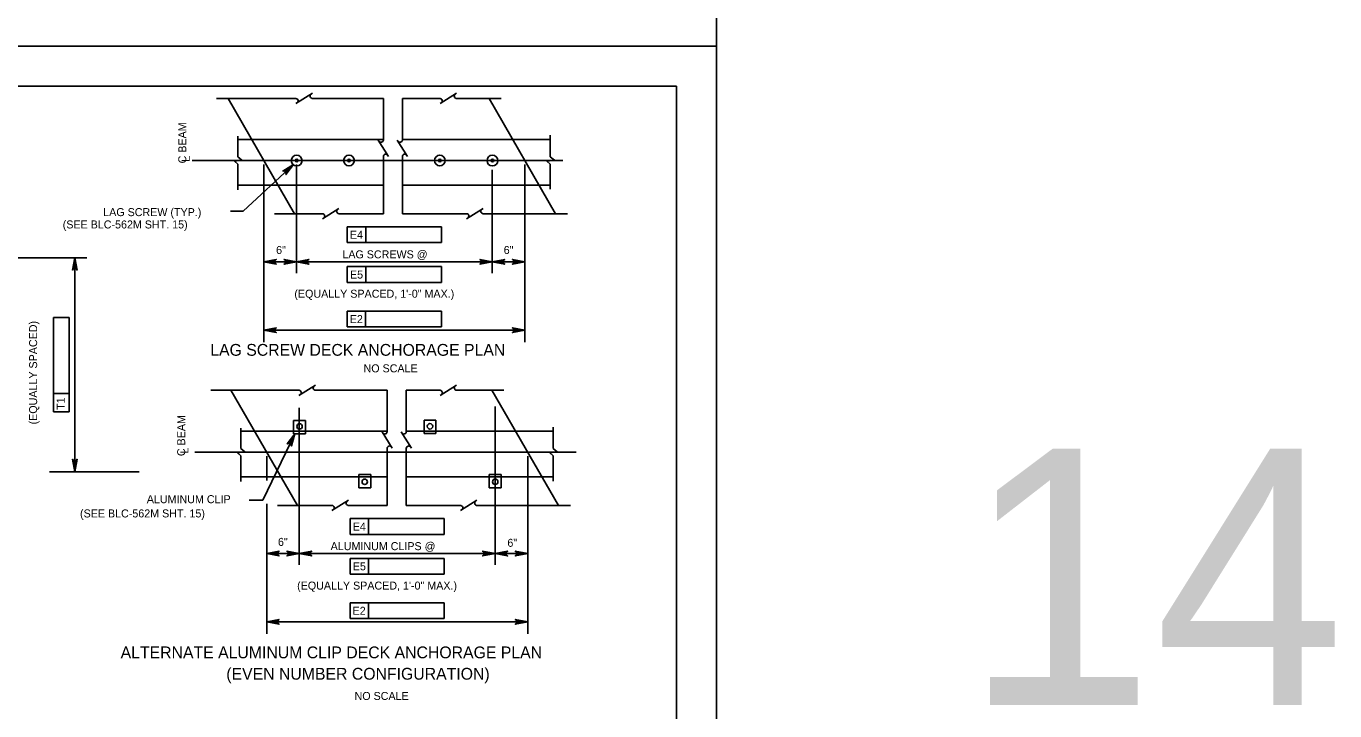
# Model space of a CAD drawing. Extents: x 638263 to 640391, y 293683 to 298655.
# Drawn here: x 639858.7 to 640349.2, y 295216.3 to 295473 of the extents above; entities that cross this region are included whole.
import ezdxf

# ---------------------------------------------------------------- set-up
doc = ezdxf.new("R2010")
doc.units = 0
for name, color, linetype in [('2', 7, 'Continuous'), ('3', 7, 'Continuous'), ('4', 7, 'Continuous'), ('8', 7, 'Continuous'), ('9', 7, 'Continuous'), ('PLT-BNDY', 7, 'Continuous')]:
    doc.layers.add(name, color=color, linetype=linetype)

# ---------------------------------------------------------------- blocks, each defined once
blk = doc.blocks.new('B')
at = {"layer": '3'}
blk.add_circle((0, 0), 0.16, dxfattribs=at)
for start, end in [(0, 180), (180, 0)]:
    blk.add_arc((0, 0), 0.0391, start, end, dxfattribs=at)

msp = doc.modelspace()

# ---------------------------------------------------------------- linework, layer by layer
at = {"layer": '2'}
for p, q in [((639316.46, 295450.46), (640102.46, 295450.46)), ((639934.36, 295445.85), (639959.32, 295402.67)), ((640032.19, 295445.85), (640057.16, 295402.67)), ((640102.46, 295450.46), (640102.46, 294886.46)), ((639935.42, 295336.5), (639960.38, 295293.31)), ((640033.25, 295336.5), (640058.22, 295293.31))]:
    msp.add_line(p, q, dxfattribs=at)
at = {"layer": '3'}
for p, q in [((639959.82, 295445.85), (639929.98, 295445.85)), ((639965.96, 295447.79), (639959.8, 295443.92)), ((639992.57, 295445.85), (639966.03, 295445.85)), ((639992.57, 295430.27), (639992.57, 295445.85)), ((639999.73, 295430.27), (639999.73, 295445.85)), ((640013.84, 295445.85), (639999.73, 295445.85)), ((640019.99, 295447.79), (640013.83, 295443.92)), ((640036.69, 295445.85), (640020.06, 295445.85)), ((639938.05, 295423.97), (639938.05, 295431.69)), ((640055.13, 295423.97), (640055.13, 295432.06)), ((639992.57, 295430.5), (639938.05, 295430.5)), ((639994.51, 295424.13), (639990.64, 295430.29)), ((640001.67, 295424.13), (639997.79, 295430.29)), ((640055.13, 295430.5), (639999.73, 295430.5)), ((639936.84, 295422.35), (639939.59, 295422.78)), ((639938.05, 295421.26), (639936.84, 295422.35)), ((639939.59, 295422.78), (639938.05, 295423.97)), ((639992.57, 295402.67), (639992.57, 295424.06)), ((639999.73, 295402.67), (639999.73, 295424.06)), ((640053.91, 295422.35), (640056.67, 295422.78)), ((640055.13, 295421.26), (640053.91, 295422.35)), ((640056.67, 295422.78), (640055.13, 295423.97)), ((639938.05, 295411.65), (639938.05, 295421.26)), ((640055.13, 295411.84), (640055.13, 295421.26)), ((639938.05, 295413.38), (639992.57, 295413.38)), ((639999.73, 295413.38), (640055.13, 295413.38)), ((639969.77, 295402.67), (639951.8, 295402.67)), ((639975.91, 295404.6), (639969.75, 295400.73)), ((639992.57, 295402.67), (639975.98, 295402.67)), ((640023.79, 295402.67), (639999.73, 295402.67)), ((640029.94, 295404.6), (640023.78, 295400.73)), ((640061.65, 295402.67), (640030.01, 295402.67)), ((639967.11, 295338.43), (639960.95, 295334.56)), ((640020.01, 295338.43), (640013.85, 295334.56)), ((639960.96, 295336.5), (639927.9, 295336.5)), ((639994.01, 295336.5), (639967.18, 295336.5)), ((639994.01, 295320.92), (639994.01, 295336.5)), ((640001.17, 295320.92), (640001.17, 295336.5)), ((640013.86, 295336.5), (640001.17, 295336.5)), ((640037.75, 295336.5), (640020.08, 295336.5)), ((639939.12, 295314.61), (639939.12, 295322.33)), ((639994.01, 295321.15), (639939.12, 295321.15)), ((639995.94, 295314.77), (639992.07, 295320.93)), ((640003.1, 295314.77), (639999.23, 295320.93)), ((640056.19, 295321.15), (640001.17, 295321.15)), ((640056.19, 295314.61), (640056.19, 295322.71)), ((639937.9, 295313), (639940.65, 295313.42)), ((639940.65, 295313.42), (639939.12, 295314.61)), ((639994.01, 295293.31), (639994.01, 295314.7)), ((640001.17, 295293.31), (640001.17, 295314.7)), ((640054.97, 295313), (640057.73, 295313.42)), ((640057.73, 295313.42), (640056.19, 295314.61)), ((639939.12, 295311.9), (639937.9, 295313)), ((639939.12, 295302.3), (639939.12, 295311.9)), ((640056.19, 295311.9), (640054.97, 295313)), ((640056.19, 295302.48), (640056.19, 295311.9)), ((639939.12, 295304.02), (639994.01, 295304.02)), ((640001.17, 295304.02), (640056.19, 295304.02)), ((639979.48, 295295.25), (639973.32, 295291.38)), ((640027.66, 295295.25), (640021.5, 295291.38)), ((639973.33, 295293.31), (639952.86, 295293.31)), ((639994.01, 295293.31), (639979.55, 295293.31)), ((640021.52, 295293.31), (640001.17, 295293.31)), ((640062.71, 295293.31), (640027.73, 295293.31))]:
    msp.add_line(p, q, dxfattribs=at)
for centre in [(639961.15, 295322.92), (640010.06, 295322.98), (639985.6, 295302.18), (640034.52, 295302.18)]:
    msp.add_circle(centre, 1.02, dxfattribs=at)
for centre, start, end in [((639959.73, 295444.94), 302.1328, 84.6714), ((639966.03, 295446.76), 120, 270), ((640013.76, 295444.94), 302.1328, 84.6714), ((640020.06, 295446.76), 120, 270), ((639991.67, 295430.35), 212.1328, 354.6714), ((639998.83, 295430.35), 212.1328, 354.6714), ((639993.48, 295424.05), 30, 180), ((640000.64, 295424.05), 30, 180), ((639969.68, 295401.76), 302.1328, 84.6714), ((639975.98, 295403.57), 120, 270), ((640023.71, 295401.76), 302.1328, 84.6714), ((640030.01, 295403.57), 120, 270), ((639967.18, 295337.4), 120, 270), ((640020.08, 295337.4), 120, 270), ((639960.88, 295335.59), 302.1328, 84.6714), ((640013.78, 295335.59), 302.1328, 84.6714), ((639993.1, 295321), 212.1328, 354.6714), ((640000.26, 295321), 212.1328, 354.6714), ((639994.92, 295314.7), 30, 180), ((640002.08, 295314.7), 30, 180), ((639979.55, 295294.22), 120, 270), ((640027.73, 295294.22), 120, 270), ((639973.25, 295292.41), 302.1328, 84.6714), ((640021.43, 295292.41), 302.1328, 84.6714)]:
    msp.add_arc(centre, 0.909, start, end, dxfattribs=at)
at = {"layer": '4'}
for p, q in [((639920.86, 295422.61), (640059.9, 295422.61)), ((639940.03, 295403.67), (639935.25, 295403.67)), ((639979.06, 295397.75), (639979.06, 295391.84)), ((639985.95, 295397.75), (639979.06, 295397.75)), ((640014.36, 295397.75), (639985.95, 295397.75)), ((639985.95, 295391.84), (639985.95, 295397.75)), ((640014.36, 295397.75), (640014.36, 295391.84)), ((639947.79, 295393.35), (639947.79, 295354.51)), ((640045.63, 295393.35), (640045.63, 295354.51)), ((639979.06, 295391.84), (640014.36, 295391.84)), ((639780.38, 295386.19), (639881.41, 295386.19)), ((639876.91, 295305.95), (639876.91, 295386.19)), ((639947.79, 295384.66), (639960.02, 295384.66)), ((639979.06, 295382.84), (639979.06, 295376.94)), ((639985.95, 295382.84), (639979.06, 295382.84)), ((639985.95, 295376.94), (639985.95, 295382.84)), ((640014.36, 295382.84), (639985.95, 295382.84)), ((640014.36, 295382.84), (640014.36, 295376.94)), ((640033.4, 295384.66), (640045.63, 295384.66)), ((639979.06, 295376.94), (640014.36, 295376.94)), ((639868.93, 295363.74), (639874.83, 295363.74)), ((639868.93, 295335.33), (639868.93, 295363.74)), ((639874.83, 295363.74), (639874.83, 295328.44)), ((639979.02, 295366.16), (639985.91, 295366.16)), ((639979.02, 295360.25), (639979.02, 295366.16)), ((639985.91, 295360.25), (639985.91, 295366.16)), ((639985.91, 295366.16), (640014.33, 295366.16)), ((640014.33, 295366.16), (640014.33, 295360.25)), ((640045.63, 295359.01), (639947.79, 295359.01)), ((640014.33, 295360.25), (639979.02, 295360.25)), ((639868.93, 295328.44), (639868.93, 295335.33)), ((639874.83, 295335.33), (639868.93, 295335.33)), ((639874.83, 295328.44), (639868.93, 295328.44)), ((639947.44, 295295.3), (639959.38, 295320.2)), ((639921.92, 295313.25), (640064.84, 295313.25)), ((639867.43, 295305.95), (639901.08, 295305.95)), ((639947.44, 295295.3), (639942.25, 295295.3)), ((639948.85, 295283.99), (639948.85, 295245.15)), ((639980.12, 295288.39), (639980.12, 295282.48)), ((639987.01, 295288.39), (639980.12, 295288.39)), ((639987.01, 295282.48), (639987.01, 295288.39)), ((640015.42, 295288.39), (639987.01, 295288.39)), ((640015.42, 295288.39), (640015.42, 295282.48)), ((640046.69, 295283.99), (640046.69, 295245.15)), ((639980.12, 295282.48), (640015.42, 295282.48)), ((639948.85, 295275.31), (639961.08, 295275.31)), ((640034.46, 295275.31), (640046.69, 295275.31)), ((639980.12, 295273.49), (639980.12, 295267.58)), ((639987.01, 295273.49), (639980.12, 295273.49)), ((640015.42, 295273.49), (639987.01, 295273.49)), ((639987.01, 295267.58), (639987.01, 295273.49)), ((640015.42, 295273.49), (640015.42, 295267.58)), ((639980.12, 295267.58), (640015.42, 295267.58)), ((639980.08, 295256.81), (639986.97, 295256.81)), ((639980.08, 295250.9), (639980.08, 295256.81)), ((639986.97, 295250.9), (639986.97, 295256.81)), ((639986.97, 295256.81), (640015.39, 295256.81)), ((640015.39, 295256.81), (640015.39, 295250.9)), ((640046.69, 295249.65), (639948.85, 295249.65)), ((640015.39, 295250.9), (639980.08, 295250.9))]:
    msp.add_line(p, q, dxfattribs=at)
for points in [[(639958.86, 295421.16), (639940.03, 295403.67)], [(639958.86, 295421.17), (639956.04, 295417.35), (639956.14, 295417.78), (639956.06, 295418.14), (639955.88, 295418.4), (639955.63, 295418.59), (639955.28, 295418.7), (639954.85, 295418.64), (639958.86, 295421.17), (639955.28, 295418.7), (639955.63, 295418.59), (639958.86, 295421.17), (639955.88, 295418.4), (639956.06, 295418.14), (639958.86, 295421.17), (639956.14, 295417.78)], [(639876.91, 295386.19), (639876.04, 295381.53), (639876.29, 295381.89), (639876.6, 295382.08), (639876.91, 295382.13), (639877.23, 295382.08), (639877.54, 295381.89), (639877.79, 295381.53), (639876.91, 295386.19), (639877.54, 295381.89), (639877.23, 295382.08), (639876.91, 295386.19), (639876.91, 295382.13), (639876.6, 295382.08), (639876.91, 295386.19), (639876.29, 295381.89)], [(639947.79, 295384.66), (639952.45, 295385.54), (639952.1, 295385.29), (639951.91, 295384.98), (639951.86, 295384.66), (639951.91, 295384.35), (639952.1, 295384.04), (639952.45, 295383.79), (639947.79, 295384.66), (639952.1, 295384.04), (639951.91, 295384.35), (639947.79, 295384.66), (639951.86, 295384.66), (639951.91, 295384.98), (639947.79, 295384.66), (639952.1, 295385.29)], [(639960.02, 295384.66), (639955.36, 295383.79), (639955.72, 295384.04), (639955.91, 295384.35), (639955.96, 295384.66), (639955.91, 295384.98), (639955.72, 295385.29), (639955.36, 295385.54), (639960.02, 295384.66), (639955.72, 295385.29), (639955.91, 295384.98), (639960.02, 295384.66), (639955.96, 295384.66), (639955.91, 295384.35), (639960.02, 295384.66), (639955.72, 295384.04)], [(639960.02, 295384.66), (639964.68, 295385.54), (639964.33, 295385.29), (639964.14, 295384.98), (639964.09, 295384.66), (639964.14, 295384.35), (639964.33, 295384.04), (639964.68, 295383.79), (639960.02, 295384.66), (639964.33, 295384.04), (639964.14, 295384.35), (639960.02, 295384.66), (639964.09, 295384.66), (639964.14, 295384.98), (639960.02, 295384.66), (639964.33, 295385.29)], [(640033.4, 295384.66), (640028.74, 295383.79), (640029.1, 295384.04), (640029.28, 295384.35), (640029.34, 295384.66), (640029.28, 295384.98), (640029.1, 295385.29), (640028.74, 295385.54), (640033.4, 295384.66), (640029.1, 295385.29), (640029.28, 295384.98), (640033.4, 295384.66), (640029.34, 295384.66), (640029.28, 295384.35), (640033.4, 295384.66), (640029.1, 295384.04)], [(640033.4, 295384.66), (640038.06, 295385.54), (640037.7, 295385.29), (640037.52, 295384.98), (640037.46, 295384.66), (640037.52, 295384.35), (640037.7, 295384.04), (640038.06, 295383.79), (640033.4, 295384.66), (640037.7, 295384.04), (640037.52, 295384.35), (640033.4, 295384.66), (640037.46, 295384.66), (640037.52, 295384.98), (640033.4, 295384.66), (640037.7, 295385.29)], [(640045.63, 295384.66), (640040.97, 295383.79), (640041.33, 295384.04), (640041.51, 295384.35), (640041.57, 295384.66), (640041.51, 295384.98), (640041.33, 295385.29), (640040.97, 295385.54), (640045.63, 295384.66), (640041.33, 295385.29), (640041.51, 295384.98), (640045.63, 295384.66), (640041.57, 295384.66), (640041.51, 295384.35), (640045.63, 295384.66), (640041.33, 295384.04)], [(639947.79, 295359.01), (639952.45, 295359.88), (639952.1, 295359.63), (639951.91, 295359.32), (639951.86, 295359.01), (639951.91, 295358.7), (639952.1, 295358.38), (639952.45, 295358.13), (639947.79, 295359.01), (639952.1, 295358.38), (639951.91, 295358.7), (639947.79, 295359.01), (639951.86, 295359.01), (639951.91, 295359.32), (639947.79, 295359.01), (639952.1, 295359.63)], [(640045.63, 295359.01), (640040.97, 295358.13), (640041.33, 295358.38), (640041.51, 295358.7), (640041.57, 295359.01), (640041.51, 295359.32), (640041.33, 295359.63), (640040.97, 295359.88), (640045.63, 295359.01), (640041.33, 295359.63), (640041.51, 295359.32), (640045.63, 295359.01), (640041.57, 295359.01), (640041.51, 295358.7), (640045.63, 295359.01), (640041.33, 295358.38)], [(639959.38, 295320.2), (639958.15, 295315.62), (639958.08, 295316.05), (639957.88, 295316.36), (639957.62, 295316.54), (639957.32, 295316.62), (639956.95, 295316.59), (639956.57, 295316.38), (639959.38, 295320.2), (639956.95, 295316.59), (639957.32, 295316.62), (639959.38, 295320.2), (639957.62, 295316.54), (639957.88, 295316.36), (639959.38, 295320.2), (639958.08, 295316.05)], [(639876.91, 295305.95), (639877.79, 295310.61), (639877.54, 295310.25), (639877.23, 295310.06), (639876.91, 295310.01), (639876.6, 295310.06), (639876.29, 295310.25), (639876.04, 295310.61), (639876.91, 295305.95), (639876.29, 295310.25), (639876.6, 295310.06), (639876.91, 295305.95), (639876.91, 295310.01), (639877.23, 295310.06), (639876.91, 295305.95), (639877.54, 295310.25)], [(639948.85, 295275.31), (639953.52, 295276.18), (639953.16, 295275.93), (639952.97, 295275.62), (639952.92, 295275.31), (639952.97, 295275), (639953.16, 295274.68), (639953.52, 295274.43), (639948.85, 295275.31), (639953.16, 295274.68), (639952.97, 295275), (639948.85, 295275.31), (639952.92, 295275.31), (639952.97, 295275.62), (639948.85, 295275.31), (639953.16, 295275.93)], [(639961.08, 295275.31), (639956.42, 295274.43), (639956.78, 295274.68), (639956.97, 295275), (639957.02, 295275.31), (639956.97, 295275.62), (639956.78, 295275.93), (639956.42, 295276.18), (639961.08, 295275.31), (639956.78, 295275.93), (639956.97, 295275.62), (639961.08, 295275.31), (639957.02, 295275.31), (639956.97, 295275), (639961.08, 295275.31), (639956.78, 295274.68)], [(639961.08, 295275.31), (639965.74, 295276.18), (639965.39, 295275.93), (639965.2, 295275.62), (639965.15, 295275.31), (639965.2, 295275), (639965.39, 295274.68), (639965.74, 295274.43), (639961.08, 295275.31), (639965.39, 295274.68), (639965.2, 295275), (639961.08, 295275.31), (639965.15, 295275.31), (639965.2, 295275.62), (639961.08, 295275.31), (639965.39, 295275.93)], [(640034.46, 295275.31), (640029.8, 295274.43), (640030.16, 295274.68), (640030.34, 295275), (640030.4, 295275.31), (640030.34, 295275.62), (640030.16, 295275.93), (640029.8, 295276.18), (640034.46, 295275.31), (640030.16, 295275.93), (640030.34, 295275.62), (640034.46, 295275.31), (640030.4, 295275.31), (640030.34, 295275), (640034.46, 295275.31), (640030.16, 295274.68)], [(640034.46, 295275.31), (640039.12, 295276.18), (640038.76, 295275.93), (640038.58, 295275.62), (640038.52, 295275.31), (640038.58, 295275), (640038.76, 295274.68), (640039.12, 295274.43), (640034.46, 295275.31), (640038.76, 295274.68), (640038.58, 295275), (640034.46, 295275.31), (640038.52, 295275.31), (640038.58, 295275.62), (640034.46, 295275.31), (640038.76, 295275.93)], [(640046.69, 295275.31), (640042.03, 295274.43), (640042.39, 295274.68), (640042.57, 295275), (640042.63, 295275.31), (640042.57, 295275.62), (640042.39, 295275.93), (640042.03, 295276.18), (640046.69, 295275.31), (640042.39, 295275.93), (640042.57, 295275.62), (640046.69, 295275.31), (640042.63, 295275.31), (640042.57, 295275), (640046.69, 295275.31), (640042.39, 295274.68)], [(639948.85, 295249.65), (639953.52, 295250.52), (639953.16, 295250.28), (639952.97, 295249.96), (639952.92, 295249.65), (639952.97, 295249.34), (639953.16, 295249.03), (639953.52, 295248.78), (639948.85, 295249.65), (639953.16, 295249.03), (639952.97, 295249.34), (639948.85, 295249.65), (639952.92, 295249.65), (639952.97, 295249.96), (639948.85, 295249.65), (639953.16, 295250.28)], [(640046.69, 295249.65), (640042.03, 295248.78), (640042.39, 295249.03), (640042.57, 295249.34), (640042.63, 295249.65), (640042.57, 295249.96), (640042.39, 295250.28), (640042.03, 295250.52), (640046.69, 295249.65), (640042.39, 295250.28), (640042.57, 295249.96), (640046.69, 295249.65), (640042.63, 295249.65), (640042.57, 295249.34), (640046.69, 295249.65), (640042.39, 295249.03)]]:
    msp.add_lwpolyline(points, dxfattribs=at)
at = {"layer": '8'}
for p, q in [((639947.79, 295421.13), (639947.79, 295380.41)), ((639960.02, 295421.13), (639960.02, 295380.41)), ((640033.4, 295419.05), (640033.4, 295380.41)), ((640045.63, 295421.13), (640045.63, 295380.41)), ((639960.02, 295384.66), (640033.4, 295384.66)), ((639961.08, 295329.97), (639961.08, 295271.06)), ((640034.46, 295330.36), (640034.46, 295271.06)), ((639944.29, 295321.15), (639944.29, 295321.15)), ((639961.14, 295322.92), (639961.14, 295322.92)), ((639948.86, 295311.77), (639948.86, 295302.63)), ((640046.69, 295311.77), (640046.69, 295271.06)), ((639953.75, 295304.02), (639953.75, 295304.02)), ((640052.02, 295304.02), (640052.02, 295304.02)), ((640034.52, 295302.18), (640034.52, 295302.18)), ((639948.86, 295293.91), (639948.86, 295271.06)), ((639961.08, 295275.31), (640034.46, 295275.31))]:
    msp.add_line(p, q, dxfattribs=at)
at = {"layer": '9'}
for p, q in [((639963.38, 295325.2), (639958.91, 295325.2)), ((639958.91, 295325.2), (639958.91, 295320.2)), ((639963.38, 295320.2), (639963.38, 295325.2)), ((640012.3, 295325.26), (640007.83, 295325.26)), ((640007.83, 295325.26), (640007.83, 295320.26)), ((640012.3, 295320.26), (640012.3, 295325.26)), ((639958.91, 295320.2), (639963.38, 295320.2)), ((640007.83, 295320.26), (640012.3, 295320.26)), ((639983.37, 295299.9), (639983.37, 295304.9)), ((639983.37, 295304.9), (639987.84, 295304.9)), ((639987.84, 295304.9), (639987.84, 295299.9)), ((640032.29, 295299.9), (640032.29, 295304.9)), ((640032.29, 295304.9), (640036.76, 295304.9)), ((640036.76, 295304.9), (640036.76, 295299.9)), ((639987.84, 295299.9), (639983.37, 295299.9)), ((640036.76, 295299.9), (640032.29, 295299.9))]:
    msp.add_line(p, q, dxfattribs=at)
at = {"layer": 'PLT-BNDY'}
for points in [[(639276.46, 296059.46), (640117.46, 296059.46), (640117.46, 295465.46), (639276.46, 295465.46)], [(639276.46, 295465.46), (640117.46, 295465.46), (640117.46, 294871.46), (639276.46, 294871.46)]]:
    msp.add_lwpolyline(points, close=True, dxfattribs=at)

# ---------------------------------------------------------------- block references
at = {"layer": '4', "xscale": 12.59905511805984, "yscale": -12.599055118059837, "rotation": 180}
for p in [(639960.09, 295422.58), (639979.7, 295422.61), (640013.74, 295422.61), (640033.46, 295422.58)]:
    msp.add_blockref('B', p, dxfattribs=at)

# ---------------------------------------------------------------- texts
at = {"layer": '4'}
for s, p in [('C BEAM', (639918.72, 295421.52)), ('L', (639920.02, 295422.15)), ('(EQUALLY SPACED)', (639862.8, 295323.69)), ('T1', (639873.14, 295329.13)), ('C BEAM', (639918.31, 295311.81)), ('L', (639919.5, 295312.79))]:
    msp.add_text(s, height=3, rotation=90, dxfattribs=at).set_placement(p)
for s, height, p in [('LAG SCREW (TYP.)', 3, (639887.58, 295401.76)), ('(SEE BLC-562M SHT. 15)', 3, (639872.4, 295397.14)), ('E4', 3, (639980.04, 295393.27)), ('6"', 3, (639952.38, 295387.56)), ('LAG SCREWS @', 3, (639977.22, 295385.93)), ('6"', 3, (640037.69, 295387.56)), ('E5', 3, (639980.07, 295378.36)), ('(EQUALLY SPACED, 1\'-0" MAX.)', 3, (639959.22, 295371.18)), ('E2', 3, (639979.98, 295361.68)), ('LAG SCREW DECK ANCHORAGE PLAN', 4.4292, (639927.7, 295349.42)), ('NO SCALE', 3, (639985.15, 295343.21)), ('14', 96, (640210.18, 295218.55)), ('ALUMINUM CLIP', 3, (639903.91, 295294.17)), ('(SEE BLC-562M SHT. 15)', 3, (639878.88, 295288.83)), ('E4', 3, (639981.1, 295283.92)), ('6"', 3, (639953.07, 295278.16)), ('ALUMINUM CLIPS @', 3, (639972.82, 295276.57)), ('6"', 3, (640039.07, 295277.82)), ('E5', 3, (639981.13, 295269.01)), ('(EQUALLY SPACED, 1\'-0" MAX.)', 3, (639960.26, 295261.78)), ('E2', 3, (639981.04, 295252.33)), ('ALTERNATE ALUMINUM CLIP DECK ANCHORAGE PLAN', 4.4292, (639894.1, 295236.03)), ('(EVEN NUMBER CONFIGURATION)', 4.4292, (639933.71, 295228.02)), ('NO SCALE', 3, (639981.78, 295220.42))]:
    msp.add_text(s, height=height, dxfattribs=at).set_placement(p)

doc.saveas('drawing.dxf')
